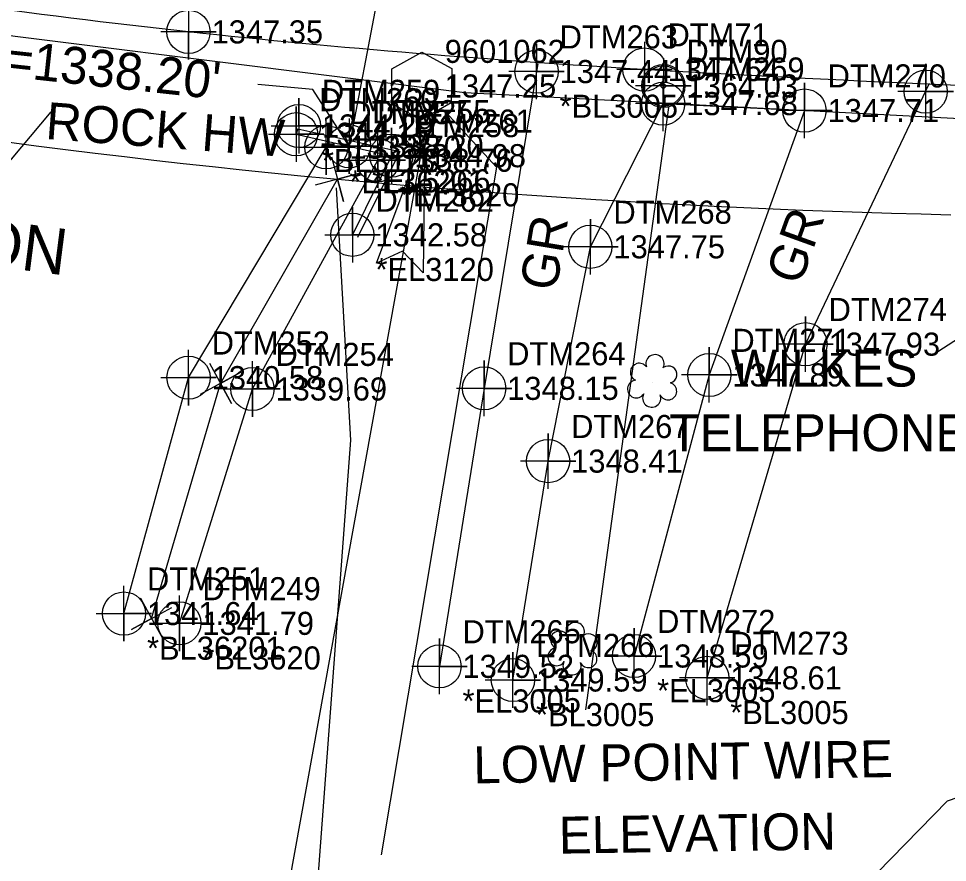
# Model space of a CAD drawing. Extents: x 1303760 to 1305114, y 904598 to 905144.
# Drawn here: x 1304141.1 to 1304241.8, y 904724.5 to 904815.9 of the extents above; entities that cross this region are included whole.
import ezdxf

# ---------------------------------------------------------------- set-up
doc = ezdxf.new("R2010")
doc.units = 0
for name, color, linetype in [('CTL GPS Vertical CELL', 7, 'Continuous'), ('CTL GPS Vertical Cogo Elevation', 7, 'Continuous'), ('CTL GPS Vertical Cogo Number', 7, 'Continuous'), ('Default', 7, 'Continuous'), ('Exist Hydro Jurisdictional Stream or Body of Water', 7, 'Continuous'), ('Exist Hydro Stream or Body of Water Cogo Comment', 7, 'Continuous'), ('Exist Hydro Stream or Body of Water Cogo Elevation', 7, 'Continuous'), ('Exist Hydro Stream or Body of Water Cogo Number', 7, 'Continuous'), ('Exist Hydro Stream or Body of Water Cogo Point CELL', 7, 'Continuous'), ('Exist Property Corner CELL', 7, 'Continuous'), ('Exist Property Line', 7, 'Continuous'), ('Exist Property Owner Text', 7, 'Continuous'), ('Exist Right of Way Line', 7, 'Continuous'), ('Exist Roads EOP', 7, 'Continuous'), ('Exist Roads EOP Cogo Elevation', 7, 'Continuous'), ('Exist Roads EOP Cogo Number', 7, 'Continuous'), ('Exist Roads EOP Cogo Point CELL', 7, 'Continuous'), ('Exist Roads Soil', 7, 'Continuous'), ('Exist Roads Soil Cogo Comment', 7, 'Continuous'), ('Exist Roads Soil Cogo Elevation', 7, 'Continuous'), ('Exist Roads Soil Cogo Number', 7, 'Continuous'), ('Exist Roads Soil Cogo Point CELL', 7, 'Continuous'), ('Exist Roads Soil Text', 7, 'Continuous'), ('Exist Structure Minor Head and End Wall', 7, 'Continuous'), ('Exist Structure Minor Head and End Wall Cogo Comment', 7, 'Continuous'), ('Exist Structure Minor Head and End Wall Cogo Elevation', 7, 'Continuous'), ('Exist Structure Minor Head and End Wall Cogo Number', 7, 'Continuous'), ('Exist Structure Minor Head and End Wall Cogo Point CELL', 7, 'Continuous'), ('Exist Structure Minor Head and End Wall Text', 7, 'Continuous'), ('Exist Structure Minor Pipes CMP 66 Inch', 7, 'Continuous'), ('Exist Structure Minor Pipes CMP 66 Inch Cogo Comment', 7, 'Continuous'), ('Exist Structure Minor Pipes CMP 66 Inch Cogo Elevation', 7, 'Continuous'), ('Exist Structure Minor Pipes CMP 66 Inch Cogo Number', 7, 'Continuous'), ('Exist Structure Minor Pipes CMP 66 Inch Cogo Point CELL', 7, 'Continuous'), ('Exist Structure Minor Pipes CMP 66 Inch Invert', 7, 'Continuous'), ('Exist Utilities Other Located Object CELL', 7, 'Continuous'), ('Exist Utilities Other Located Object Leader', 7, 'Continuous'), ('Exist Utilities Other Located Object Text', 7, 'Continuous'), ('Exist Utilities Power UG Cable Cogo Elevation', 7, 'Continuous'), ('Exist Utilities Power UG Cable Cogo Number', 7, 'Continuous'), ('Exist Utilities Power UG Cable Cogo Point CELL', 7, 'Continuous'), ('Exist Utilities Telephone Pole Leader', 7, 'Continuous'), ('Exist Utilities Telephone Pole Text', 7, 'Continuous'), ('Exist Utilities Telephone UG Cable', 7, 'Continuous'), ('Exist Utilities Telephone UG FO', 7, 'Continuous'), ('Exist Vegetation Shrub CELL', 7, 'Continuous'), ('Exist Vegetation Woods Line', 7, 'Continuous'), ('Old_Level_11', 7, 'Continuous')]:
    doc.layers.add(name, color=color, linetype=linetype)

msp = doc.modelspace()

# ---------------------------------------------------------------- linework, layer by layer
at = {"layer": 'CTL GPS Vertical CELL'}
msp.add_line((1304184.8, 904808.61), (1304184.8, 904808.61), dxfattribs=at)
msp.add_lwpolyline([(1304181.56, 904810.48), (1304184.81, 904812.29), (1304188.06, 904810.5), (1304188.01, 904806.78), (1304184.76, 904804.89), (1304181.56, 904806.7)], close=True, dxfattribs=at)
at = {"layer": 'Default'}
msp.add_line((1304169.58, 904717.38), (1304185.15, 904803.42), dxfattribs=at)
at = {"layer": 'Exist Hydro Jurisdictional Stream or Body of Water'}
for points in [[(1304152.55, 904751.47), (1304159.55, 904777.02), (1304174.47, 904801.98)], [(1304158.55, 904750.41), (1304166.47, 904775.79), (1304180.06, 904800.57)]]:
    msp.add_lwpolyline(points, dxfattribs=at)
at = {"layer": 'Exist Hydro Stream or Body of Water Cogo Point CELL'}
for points in [[(1304171.47, 904801.98), (1304177.47, 904801.98), (1304174.47, 904801.98), (1304174.47, 904798.98), (1304174.47, 904804.98)], [(1304177.06, 904800.57), (1304183.06, 904800.57), (1304180.06, 904800.57), (1304180.06, 904797.57), (1304180.06, 904803.57)], [(1304156.55, 904777.02), (1304162.55, 904777.02), (1304159.55, 904777.02), (1304159.55, 904774.02), (1304159.55, 904780.02)], [(1304163.47, 904775.79), (1304169.47, 904775.79), (1304166.47, 904775.79), (1304166.47, 904772.79), (1304166.47, 904778.79)], [(1304149.55, 904751.47), (1304155.55, 904751.47), (1304152.55, 904751.47), (1304152.55, 904748.47), (1304152.55, 904754.47)], [(1304155.55, 904750.41), (1304161.55, 904750.41), (1304158.55, 904750.41), (1304158.55, 904747.41), (1304158.55, 904753.41)]]:
    msp.add_lwpolyline(points, dxfattribs=at)
for centre in [(1304174.47, 904801.98), (1304180.06, 904800.57), (1304159.55, 904777.02), (1304166.47, 904775.79), (1304152.55, 904751.47), (1304158.55, 904750.41)]:
    msp.add_circle(centre, 2.34, dxfattribs=at)
at = {"layer": 'Exist Property Corner CELL'}
for p, q in [((1304175.68, 904798.52), (1304175.68, 904798.52)), ((1304163.01, 904776.4), (1304163.01, 904776.4)), ((1304155.55, 904750.94), (1304155.55, 904750.94))]:
    msp.add_line(p, q, dxfattribs=at)
for points in [[(1304175.02, 904800.93), (1304176.33, 904796.1), (1304175.68, 904798.52), (1304178.09, 904799.17), (1304173.27, 904797.86)], [(1304161.81, 904778.6), (1304164.21, 904774.21), (1304163.01, 904776.4), (1304165.2, 904777.6), (1304160.81, 904775.2)], [(1304156.75, 904748.75), (1304154.35, 904753.13), (1304155.55, 904750.94), (1304153.36, 904749.74), (1304157.74, 904752.14)]]:
    msp.add_lwpolyline(points, dxfattribs=at)
at = {"layer": 'Exist Property Line'}
for p, q in [((1304163.01, 904776.4), (1304175.68, 904798.52)), ((1304155.55, 904750.94), (1304163.01, 904776.4))]:
    msp.add_line(p, q, dxfattribs=at)
at = {"layer": 'Exist Right of Way Line'}
msp.add_arc((1304263.29, 905736.16), 941.73, 256.22599, 268.71327, dxfattribs=at)
at = {"layer": 'Exist Roads EOP'}
msp.add_spline([(1304262.03, 904807.84), (1304208.94, 904810.39), (1304159.54, 904814.47), (1304108.78, 904821.63), (1304061, 904830.95)], degree=3, dxfattribs=at)
at = {"layer": 'Exist Roads EOP Cogo Point CELL'}
for points in [[(1304159.54, 904817.47), (1304159.54, 904811.47), (1304159.54, 904814.47), (1304162.54, 904814.47), (1304156.54, 904814.47)], [(1304208.94, 904813.39), (1304208.94, 904807.39), (1304208.94, 904810.39), (1304211.94, 904810.39), (1304205.94, 904810.39)]]:
    msp.add_lwpolyline(points, dxfattribs=at)
for centre in [(1304159.54, 904814.47), (1304208.94, 904810.39)]:
    msp.add_circle(centre, 2.34, dxfattribs=at)
at = {"layer": 'Exist Roads Soil'}
for points in [[(1304197.4, 904811.06), (1304191.57, 904775.86), (1304186.73, 904745.75)], [(1304215.74, 904744.5), (1304226.39, 904780.64), (1304239.84, 904808.91)], [(1304194.69, 904744.27), (1304198.5, 904767.98), (1304203.08, 904791.19), (1304210.97, 904806.7), (1304226.28, 904805.95), (1304215.97, 904777.31), (1304207.81, 904746.87)]]:
    msp.add_lwpolyline(points, dxfattribs=at)
at = {"layer": 'Exist Roads Soil Cogo Point CELL'}
for points in [[(1304197.25, 904807.17), (1304197.25, 904813.17), (1304197.25, 904810.17), (1304200.25, 904810.17), (1304194.25, 904810.17)], [(1304239.41, 904805), (1304239.41, 904811), (1304239.41, 904808), (1304242.41, 904808), (1304236.41, 904808)], [(1304210.97, 904803.7), (1304210.97, 904809.7), (1304210.97, 904806.7), (1304213.97, 904806.7), (1304207.97, 904806.7)], [(1304226.28, 904802.95), (1304226.28, 904808.95), (1304226.28, 904805.95), (1304229.28, 904805.95), (1304223.28, 904805.95)], [(1304203.08, 904788.19), (1304203.08, 904794.19), (1304203.08, 904791.19), (1304206.08, 904791.19), (1304200.08, 904791.19)], [(1304226.39, 904777.64), (1304226.39, 904783.64), (1304226.39, 904780.64), (1304229.39, 904780.64), (1304223.39, 904780.64)], [(1304215.97, 904774.31), (1304215.97, 904780.31), (1304215.97, 904777.31), (1304218.97, 904777.31), (1304212.97, 904777.31)], [(1304191.57, 904772.86), (1304191.57, 904778.86), (1304191.57, 904775.86), (1304194.57, 904775.86), (1304188.57, 904775.86)], [(1304198.5, 904764.98), (1304198.5, 904770.98), (1304198.5, 904767.98), (1304201.5, 904767.98), (1304195.5, 904767.98)], [(1304207.81, 904743.87), (1304207.81, 904749.87), (1304207.81, 904746.87), (1304210.81, 904746.87), (1304204.81, 904746.87)], [(1304186.73, 904742.75), (1304186.73, 904748.75), (1304186.73, 904745.75), (1304189.73, 904745.75), (1304183.73, 904745.75)], [(1304215.74, 904741.5), (1304215.74, 904747.5), (1304215.74, 904744.5), (1304218.74, 904744.5), (1304212.74, 904744.5)], [(1304194.69, 904741.27), (1304194.69, 904747.27), (1304194.69, 904744.27), (1304197.69, 904744.27), (1304191.69, 904744.27)]]:
    msp.add_lwpolyline(points, dxfattribs=at)
for centre in [(1304197.25, 904810.17), (1304239.41, 904808), (1304210.97, 904806.7), (1304226.28, 904805.95), (1304203.08, 904791.19), (1304226.39, 904780.64), (1304215.97, 904777.31), (1304191.57, 904775.86), (1304198.5, 904767.98), (1304207.81, 904746.87), (1304186.73, 904745.75), (1304194.69, 904744.27), (1304215.74, 904744.5)]:
    msp.add_circle(centre, 2.34, dxfattribs=at)
at = {"layer": 'Exist Structure Minor Head and End Wall'}
for p, q in [((1304171.4, 904803.98), (1304182.44, 904801.5)), ((1304182.44, 904801.5), (1304177.87, 904792.21))]:
    msp.add_line(p, q, dxfattribs=at)
for points in [[(1304171.4, 904803.98), (1304171.2, 904803.38)], [(1304171.2, 904803.38), (1304181.52, 904801.06)], [(1304181.52, 904801.06), (1304177.3, 904792.49)]]:
    msp.add_lwpolyline(points, dxfattribs=at)
at = {"layer": 'Exist Structure Minor Head and End Wall Cogo Point CELL'}
for points in [[(1304168.5, 904804.28), (1304174.5, 904804.28), (1304171.5, 904804.28), (1304171.5, 904807.28), (1304171.5, 904801.28)], [(1304168.2, 904803.38), (1304174.2, 904803.38), (1304171.2, 904803.38), (1304171.2, 904806.38), (1304171.2, 904800.38)], [(1304178.52, 904801.06), (1304184.52, 904801.06), (1304181.52, 904801.06), (1304181.52, 904804.06), (1304181.52, 904798.06)], [(1304174.3, 904792.49), (1304180.3, 904792.49), (1304177.3, 904792.49), (1304177.3, 904795.49), (1304177.3, 904789.49)]]:
    msp.add_lwpolyline(points, dxfattribs=at)
for centre in [(1304171.2, 904803.38), (1304171.5, 904804.28), (1304181.52, 904801.06), (1304177.3, 904792.49)]:
    msp.add_circle(centre, 2.34, dxfattribs=at)
at = {"layer": 'Exist Structure Minor Pipes CMP 66 Inch'}
msp.add_line((1304184.63, 904842.19), (1304176.94, 904802.08), dxfattribs=at)
at = {"layer": 'Exist Structure Minor Pipes CMP 66 Inch Cogo Point CELL'}
msp.add_lwpolyline([(1304176.94, 904805.08), (1304176.94, 904799.08), (1304176.94, 904802.08), (1304179.94, 904802.08), (1304173.94, 904802.08)], dxfattribs=at)
msp.add_circle((1304176.94, 904802.08), 2.34, dxfattribs=at)
at = {"layer": 'Exist Structure Minor Pipes CMP 66 Inch Invert'}
msp.add_lwpolyline([(1304176.94, 904802.08), (1304173.02, 904808.23), (1304167.05, 904808.77)], dxfattribs=at)
at = {"layer": 'Exist Utilities Other Located Object CELL'}
for radius in [2.18, 0.24]:
    msp.add_circle((1304210.99, 904808.61), radius, dxfattribs=at)
at = {"layer": 'Exist Utilities Other Located Object Leader'}
msp.add_line((1304211.53, 904806.27), (1304202.57, 904741.05), dxfattribs=at)
at = {"layer": 'Exist Utilities Power UG Cable Cogo Point CELL'}
msp.add_lwpolyline([(1304210.99, 904811.61), (1304210.99, 904805.61), (1304210.99, 904808.61), (1304213.99, 904808.61), (1304207.99, 904808.61)], dxfattribs=at)
msp.add_circle((1304210.99, 904808.61), 2.34, dxfattribs=at)
at = {"layer": 'Exist Utilities Telephone Pole Leader'}
msp.add_line((1304266.04, 904796.34), (1304240.22, 904779.48), dxfattribs=at)
at = {"layer": 'Exist Utilities Telephone UG Cable'}
msp.add_lwpolyline([(1304187.35, 904805.85), (1304192.93, 904799.82), (1304180.43, 904725.33)], dxfattribs=at)
at = {"layer": 'Exist Utilities Telephone UG FO'}
msp.add_lwpolyline([(1304119.72, 904816.65), (1304189.49, 904807.92), (1304258.23, 904804.29), (1304258.45, 904799.82), (1304267.81, 904798.93)], dxfattribs=at)
at = {"layer": 'Exist Vegetation Shrub CELL'}
for p, q in [((1304209.86, 904776.48), (1304209.86, 904776.48)), ((1304201.23, 904747.48), (1304201.23, 904747.48))]:
    msp.add_line(p, q, dxfattribs=at)
for centre, radius, start, end in [((1304208.38, 904777.61), 0.968, 35.8908, 245.4216), ((1304210.09, 904778.52), 0.99, 334.8391, 200.4717), ((1304211.53, 904777.35), 0.929, 284.4567, 126.0861), ((1304208.06, 904775.78), 0.955, 95.1099, 327.9534), ((1304211.5, 904775.55), 0.937, 204.9913, 73.4601), ((1304209.73, 904774.8), 0.984, 151.2797, 21.387), ((1304201.45, 904749.52), 0.99, 334.8391, 200.4717), ((1304199.74, 904748.61), 0.968, 35.8908, 245.4216), ((1304202.9, 904748.35), 0.929, 284.4567, 126.0861), ((1304199.43, 904746.77), 0.955, 95.1099, 327.9534), ((1304202.86, 904746.55), 0.937, 204.9913, 73.4601), ((1304201.1, 904745.8), 0.984, 151.2797, 21.387)]:
    msp.add_arc(centre, radius, start, end, dxfattribs=at)
at = {"layer": 'Exist Vegetation Woods Line'}
for points in [[(1304116.45, 904672.02), (1304110.21, 904750.5), (1304107.63, 904761.7), (1304144.68, 904805.82)], [(1304214.49, 904670.67), (1304223.46, 904712.45), (1304241.79, 904731.19), (1304279.23, 904744.08), (1304302.63, 904753.84), (1304307.7, 904771.41), (1304284.69, 904785.85), (1304278.06, 904793.66), (1304286.25, 904802.64), (1304305.75, 904801.08), (1304330.13, 904756.77), (1304396.43, 904691.95)], [(1304175.54, 904797.57), (1304177.1, 904770.24), (1304171.64, 904697.22)]]:
    msp.add_lwpolyline(points, dxfattribs=at)
at = {"layer": 'Old_Level_11'}
msp.add_lwpolyline([(1304179.9, 904789.41), (1304185.15, 904803.42), (1304184.96, 904788.37), (1304182.73, 904790.71)], close=True, dxfattribs=at)

# ---------------------------------------------------------------- texts
at = {"layer": 'CTL GPS Vertical Cogo Elevation'}
msp.add_text('1347.25', height=2.5, dxfattribs=at).set_placement((1304187.3, 904807.36))
at = {"layer": 'CTL GPS Vertical Cogo Number'}
msp.add_text('9601062', height=2.5, dxfattribs=at).set_placement((1304187.3, 904811.11))
at = {"layer": 'Exist Hydro Stream or Body of Water Cogo Comment'}
for s, p in [('*EL36201', (1304176.97, 904796.98)), ('*EL3620', (1304182.56, 904795.57)), ('*BL36201', (1304155.05, 904746.47)), ('*BL3620', (1304161.05, 904745.41))]:
    msp.add_text(s, height=2.5, dxfattribs=at).set_placement(p)
at = {"layer": 'Exist Hydro Stream or Body of Water Cogo Elevation'}
for s, p in [('1338.70', (1304176.97, 904800.73)), ('1338.76', (1304182.56, 904799.32)), ('1340.58', (1304162.05, 904775.77)), ('1339.69', (1304168.97, 904774.54)), ('1341.64', (1304155.05, 904750.22)), ('1341.79', (1304161.05, 904749.16))]:
    msp.add_text(s, height=2.5, dxfattribs=at).set_placement(p)
at = {"layer": 'Exist Hydro Stream or Body of Water Cogo Number'}
for s, p in [('DTM257', (1304176.97, 904804.48)), ('DTM258', (1304182.56, 904803.07)), ('DTM252', (1304162.05, 904779.52)), ('DTM254', (1304168.97, 904778.29)), ('DTM251', (1304155.05, 904753.97)), ('DTM249', (1304161.05, 904752.91))]:
    msp.add_text(s, height=2.5, dxfattribs=at).set_placement(p)
at = {"layer": 'Exist Property Owner Text'}
msp.add_text('LOUIS M. PATTERSON', height=5, rotation=352.6864, dxfattribs=at).set_placement((1304074.58, 904797.27))
at = {"layer": 'Exist Roads EOP Cogo Elevation'}
for s, p in [('1347.35', (1304162.04, 904813.22)), ('1347.64', (1304211.44, 904809.14))]:
    msp.add_text(s, height=2.5, dxfattribs=at).set_placement(p)
at = {"layer": 'Exist Roads EOP Cogo Number'}
msp.add_text('DTM71', height=2.5, dxfattribs=at).set_placement((1304211.44, 904812.89))
at = {"layer": 'Exist Roads Soil Cogo Comment'}
for s, p in [('*BL3005', (1304199.75, 904805.17)), ('*EL3005', (1304210.31, 904741.87)), ('*EL3005', (1304189.23, 904740.75)), ('*BL3005', (1304197.19, 904739.27)), ('*BL3005', (1304218.24, 904739.5))]:
    msp.add_text(s, height=2.5, dxfattribs=at).set_placement(p)
at = {"layer": 'Exist Roads Soil Cogo Elevation'}
for s, p in [('1347.44', (1304199.75, 904808.92)), ('1347.68', (1304213.47, 904805.45)), ('1347.71', (1304228.78, 904804.7)), ('1347.75', (1304205.58, 904789.94)), ('1347.93', (1304228.89, 904779.4)), ('1347.89', (1304218.47, 904776.06)), ('1348.15', (1304194.07, 904774.61)), ('1348.41', (1304201, 904766.73)), ('1348.59', (1304210.31, 904745.62)), ('1349.52', (1304189.23, 904744.5)), ('1349.59', (1304197.19, 904743.02)), ('1348.61', (1304218.24, 904743.25))]:
    msp.add_text(s, height=2.5, dxfattribs=at).set_placement(p)
at = {"layer": 'Exist Roads Soil Cogo Number'}
for s, p in [('DTM263', (1304199.75, 904812.67)), ('DTM269', (1304213.47, 904809.2)), ('DTM270', (1304228.78, 904808.45)), ('DTM268', (1304205.58, 904793.69)), ('DTM274', (1304228.89, 904783.15)), ('DTM271', (1304218.47, 904779.81)), ('DTM264', (1304194.07, 904778.36)), ('DTM267', (1304201, 904770.48)), ('DTM272', (1304210.31, 904749.37)), ('DTM265', (1304189.23, 904748.25)), ('DTM273', (1304218.24, 904747)), ('DTM266', (1304197.19, 904746.77))]:
    msp.add_text(s, height=2.5, dxfattribs=at).set_placement(p)
at = {"layer": 'Exist Roads Soil Text'}
for rotation, p in [(70.2018, (1304225.79, 904786.88)), (80.6087, (1304199.38, 904786.29))]:
    msp.add_text('GR', height=4, rotation=rotation, dxfattribs=at).set_placement(p)
at = {"layer": 'Exist Structure Minor Head and End Wall Cogo Comment'}
for s, p in [('*BL3120', (1304174, 904799.28)), ('*EL3120', (1304179.8, 904787.49))]:
    msp.add_text(s, height=2.5, dxfattribs=at).set_placement(p)
at = {"layer": 'Exist Structure Minor Head and End Wall Cogo Elevation'}
for s, p in [('1344.29', (1304174, 904803.03)), ('1344.15', (1304173.7, 904802.13)), ('1344.98', (1304184.02, 904799.81)), ('1342.58', (1304179.8, 904791.24))]:
    msp.add_text(s, height=2.5, dxfattribs=at).set_placement(p)
at = {"layer": 'Exist Structure Minor Head and End Wall Cogo Number'}
for s, p in [('DTM259', (1304174, 904806.78)), ('DTM260', (1304173.7, 904805.88)), ('DTM261', (1304184.02, 904803.56)), ('DTM262', (1304179.8, 904794.99))]:
    msp.add_text(s, height=2.5, dxfattribs=at).set_placement(p)
at = {"layer": 'Exist Structure Minor Head and End Wall Text'}
msp.add_text('ROCK HW', height=4, rotation=355.7006, dxfattribs=at).set_placement((1304143.98, 904802.88))
at = {"layer": 'Exist Structure Minor Pipes CMP 66 Inch Cogo Comment'}
msp.add_text('*EL5266', height=2.5, dxfattribs=at).set_placement((1304179.44, 904797.08))
at = {"layer": 'Exist Structure Minor Pipes CMP 66 Inch Cogo Elevation'}
msp.add_text('1338.20', height=2.5, dxfattribs=at).set_placement((1304179.44, 904800.83))
at = {"layer": 'Exist Structure Minor Pipes CMP 66 Inch Cogo Number'}
msp.add_text('DTM255', height=2.5, dxfattribs=at).set_placement((1304179.44, 904804.58))
at = {"layer": 'Exist Structure Minor Pipes CMP 66 Inch Invert'}
msp.add_text("INV=1338.20'", height=4, rotation=353.8071, dxfattribs=at).set_placement((1304130.57, 904810.64))
at = {"layer": 'Exist Utilities Other Located Object Text'}
for s, p in [('LOW POINT WIRE ', (1304190.43, 904733.07)), ('ELEVATION', (1304199.69, 904725.46))]:
    msp.add_text(s, height=4, rotation=0.8742, dxfattribs=at).set_placement(p)
at = {"layer": 'Exist Utilities Power UG Cable Cogo Elevation'}
msp.add_text('1364.03', height=2.5, dxfattribs=at).set_placement((1304213.49, 904807.36))
at = {"layer": 'Exist Utilities Power UG Cable Cogo Number'}
msp.add_text('DTM90', height=2.5, dxfattribs=at).set_placement((1304213.49, 904811.11))
at = {"layer": 'Exist Utilities Telephone Pole Text'}
for s, p in [('WILKES ', (1304218.3, 904776.05)), ('TELEPHONE', (1304211.64, 904769.05))]:
    msp.add_text(s, height=4, dxfattribs=at).set_placement(p)

doc.saveas('drawing.dxf')
